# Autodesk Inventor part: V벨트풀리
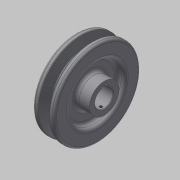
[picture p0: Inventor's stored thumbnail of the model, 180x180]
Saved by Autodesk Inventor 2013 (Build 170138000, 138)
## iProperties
Created: 2015-11
Part Number: V벨트풀리
Material: 강철, 탄소
Document SubType Name: Modeling
Designer: mduedu
Density: 1 g/cm^3
Author: mduedu
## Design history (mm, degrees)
sketch "스케치1"
  geometry: L1 (-9.5, 0)-(9.5, 0); L2 (0, 0)-(0, 37.7); L3 (-4.825, 37.7)-(-9.5, 37.7); L4 (-9.5, 37.7)-(-9.5, 0); L5 (0, 28.7)-(-2.074, 28.7); L6 (-2.074, 28.7)-(-4.825, 37.7); L7 (4.825, 37.7)-(9.5, 37.7); L8 (9.5, 37.7)-(9.5, 0); L9 (0, 28.7)-(2.074, 28.7); L10 (2.074, 28.7)-(4.825, 37.7); L11 (-9.5, 35)-(9.5, 35); 3 further points
  constraints: 22 end point, 7 point on line, 4 perpendicular, 3 symmetric about line, 1 coincident, 1 horizontal, 1 horizontal alignment, 1 midpoint, 1 vertical
  dimensions: "d0" = 19 distance of L1.start L1.end; "d2" = 75.4 diameter of L2.end L1 (derived); "d3" = 34 deg angle of L10 L6; "d4" = 6.3 distance between parallel lines of L11 L9; "d5" = 2.7 distance between parallel lines of L7 L11; "d6" = 8 distance of point (4, 35) point (-4, 35); "d7" = 70 diameter of L11 L1
revolve "회전1" sketch "스케치1" stored, may be unused: angle "d8" = 90 deg
sketch "스케치2"
  geometry: C1 r 24 at (0, 0); C2 r 13 at (0, 0); 1 further point
  constraints: 2 centre point, 2 coincident
  dimensions: "d9" = 48 diameter of C1; "d10" = 26 diameter of C2
extrude "돌출1" cut sketch "스케치2" distance "d11" = 6; taper "d12" = 0 deg
extrude "돌출3" join sketch "스케치2" distance "d37" = 6; taper "d38" = 0 deg
fillet "모깎기1" dims "d13" = 3
fillet "모깎기2" dims "d14" = 3
fillet "모깎기3" dims "d15" = 1, "d16" = 0.5, "d17" = 2
hole "구멍1" diameter "d20" = 16; stored, may be unused: countersink angle "d24" = 90 deg, drill point angle "d26" = 118 deg; dims "d21" = 6, "d22" = 4, "d23" = 2, "d25" = 8, "d53" = 10, "d54" = 10
sketch "스케치3"
  geometry: L1 (-2.5, 0)-(2.5, 0); L2 (2.5, 0)-(2.5, 10.3); L3 (2.5, 10.3)-(-2.5, 10.3); L4 (-2.5, 10.3)-(-2.5, 0); 2 further points
  constraints: 8 end point, 2 parallel, 1 coincident, 1 horizontal, 1 midpoint, 1 perpendicular
  dimensions: "d27" = 5 distance of L2.end L3.end; "d29" = 10.3 distance of L3.end L1.start
extrude "돌출2" cut sketch "스케치3" stored distance "d30" = 6; taper "d31" = 0 deg
node "작업 평면1"
sketch "스케치4"
  geometry: L1 (19, -27)-(19, 27) reference; 2 further points
  constraints: 1 horizontal alignment
  dimensions: "d52" = 22 distance from line of L1 point (-3, 0)
hole "구멍2" sketch "스케치4" at (-3, 0) diameter "d42" = 2.459; stored, may be unused: countersink angle "d46" = 90 deg, drill point angle "d48" = 118 deg; dims "d43" = 6, "d44" = 4, "d45" = 2, "d47" = 8
chamfer "모따기3" distance "d58" = 0.5; stored, may be unused: second distance "d59" = 2, angle "d60" = 45 deg
node "솔리드1"
mirror "대칭1"
